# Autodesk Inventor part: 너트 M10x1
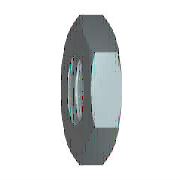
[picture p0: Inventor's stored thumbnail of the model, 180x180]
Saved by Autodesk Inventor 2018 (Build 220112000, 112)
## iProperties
Created: 2012-02
Part Number: 너트 M10x1
Material: 강철, 연강
Description: 6각 가는 너트 - 이중 모따기(부품 등급 A) - 정밀 나사산
Document SubType Name: Modeling
Standard: JIS B 1181
Designer: mduedu
Standards Organization: JIS
Language: ko-KR
Size Designation: M10x1
Categories: <MemberInstance><Categories><Category DisplayName="조임쇠" InternalName="e4da775c-781d-43d5-af7c-5136215cf5a6" Mnemonic="FSTN"><Category DisplayName="너트" InternalN
Density: 7.86 g/cm^3
Appearance: 강철
IsCustomPart: 1
Author: mduedu
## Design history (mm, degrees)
node "MSC_A1"
node "MSC_PT1"
node "MSC_PT2"
node "MSC_PF1"
body "Solid1"
sketch "스케치1"
  geometry: L1 (8, 4.619)-(8, -4.619); L2 (8, -4.619)-(0, -9.238); L3 (0, -9.238)-(-8, -4.619); L4 (-8, -4.619)-(-8, 4.619); L5 (-8, 4.619)-(0, 9.238); L6 (0, 9.238)-(8, 4.619); C1 r 8 at (0, 0); 2 further points
  constraints: 12 end point, 2 coincident, 1 centre point, 1 tangent, 1 vertical, 11 other
  dimensions: "d0" = 16 diameter of C1 (= ParS)
extrude "돌출1" new body sketch "스케치1" distance "d1" = 5 (= M); taper "d2" = 0 deg
sketch "스케치2"
  geometry: L1 (-8, 4.619)-(0, 9.238) reference; L2 (0, -9.238)-(-8, -4.619) reference; L3 (-8, 4.619)-(8, -4.619); L4 (-8, -4.619)-(8, 4.619); 1 further point
  constraints: 4 end point, 2 midpoint, 2 parallel
hole "구멍1" sketch "스케치2" diameter "d3" = 8.91747; stored, may be unused: countersink angle "d7" = 90 deg, drill point angle "d9" = 118 deg; dims "d4" = 6, "d5" = 4, "d6" = 2, "d8" = 8
chamfer "모따기1" distance "d10" = 0.5 (= 0.5 x PTC); stored, may be unused: second distance "d11" = 2, angle "d12" = 45 deg
revolve "회전1" stored, may be unused: angle "d15" = 90 deg
sketch "스케치3"
  geometry: L1 (-9.238, 5)-(-9.238, 4.285); L2 (-9.238, 4.285)-(-8, 5); L3 (-8, 5)-(-9.238, 5); L4 (-9.238, 0.715)-(-9.238, 0); L5 (-9.238, 0)-(-8, 0); L6 (-8, 0)-(-9.238, 0.715); L7 (0, 6)-(0, -1) reference; L8 (-4.619, 5)-(-9.238, 5) reference; L9 (-4.619, 0)-(-9.238, 0) reference; L10 (-9.238, 0)-(-9.238, 5) reference
  constraints: 12 end point, 4 collinear, 3 perpendicular, 2 equal length, 1 vertical
  dimensions: "d13" = 30 deg angle of L2 L3; "d14" = 8 distance from line of L2.end L7 (= 0.5 x ParS)
other parameters: "ParS" = 16 [user parameter; used in 2 equation terms], "M" = 5 [user parameter; used in 1 equation term], "PTC" = 1 [user parameter; used in 1 equation term], "d17" = 0, "d18" = 0, "d19" = 0, "d20" = 0, "d21" = 0, "d22" = 0, "d23" = 0
